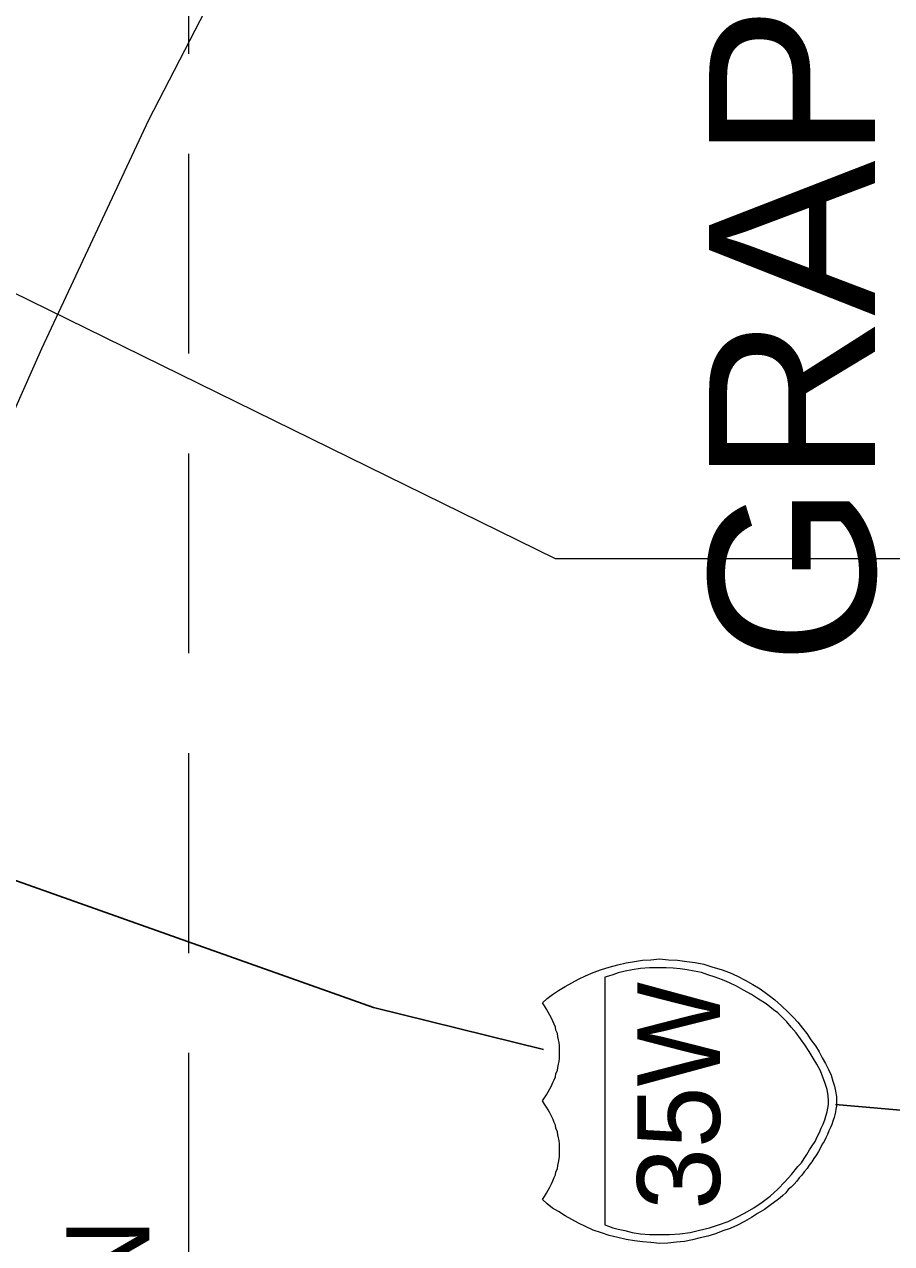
# Model space of a CAD drawing. Extents: x 2363323 to 2367082, y 6956018 to 6980837.
# Drawn here: x 2365838.7 to 2365892.1, y 6980582.6 to 6980657.7 of the extents above; entities that cross this region are included whole.
import ezdxf

# ---------------------------------------------------------------- set-up
doc = ezdxf.new("R2010")
doc.units = 0
doc.header["$LTSCALE"] = 4.1
doc.linetypes.add('MEDIUM_DASHED', pattern=[4.5, 3, -1.5])
doc.layers.add('62', color=7, linetype='Continuous', lineweight=13)
doc.layers.add('63', color=7, linetype='Continuous', lineweight=13)

msp = doc.modelspace()

# ---------------------------------------------------------------- linework, layer by layer
at = {"layer": '62', "linetype": 'MEDIUM_DASHED'}
msp.add_line((2365848.822, 6980834.218), (2365848.821, 6980385.954), dxfattribs=at)
at = {"layer": '62'}
msp.add_line((2365902.216, 6980624.792), (2365871.414, 6980624.792), dxfattribs=at)
at = {"layer": '62', "lineweight": 25}
for p, q in [((2365860.208, 6980597.16), (2365870.668, 6980594.571)), ((2365899.359, 6980590.251), (2365888.649, 6980591.198))]:
    msp.add_line(p, q, dxfattribs=at)
at = {"layer": '62'}
for points in [[(2365809.287, 6980449.612), (2365804.356, 6980460.212), (2365802.512, 6980474.5), (2365809.894, 6980490.59), (2365810.838, 6980501.526), (2365817.837, 6980515.14), (2365822.54, 6980524.522), (2365825.554, 6980532.603), (2365827.714, 6980543.964), (2365828.59, 6980553.189), (2365829.04, 6980565.342), (2365828.5, 6980579.562), (2365830.796, 6980597.678), (2365831.606, 6980609.468), (2365833.203, 6980622.902), (2365839.778, 6980637.732), (2365846.368, 6980651.814), (2365853.028, 6980664.688), (2365864.278, 6980679.314), (2365871.414, 6980689.148), (2365878.929, 6980701.188), (2365885.793, 6980708.072)], [(2365871.414, 6980624.792), (2365815.923, 6980652.02), (2365754.402, 6980665.14)], [(2365871.054, 6980592.164), (2365871.166, 6980592.345), (2365871.256, 6980592.548), (2365871.326, 6980592.704), (2365871.416, 6980592.906), (2365871.436, 6980593.108), (2365871.526, 6980593.288), (2365871.55, 6980593.468), (2365871.596, 6980593.67), (2365871.64, 6980593.85), (2365871.662, 6980594.054), (2365871.663, 6980594.234), (2365871.662, 6980594.436), (2365871.662, 6980594.616), (2365871.662, 6980594.796), (2365871.639, 6980595.02), (2365871.596, 6980595.178), (2365871.55, 6980595.358), (2365871.526, 6980595.562), (2365871.436, 6980595.764), (2365871.416, 6980595.945), (2365871.324, 6980596.148), (2365871.256, 6980596.328), (2365871.166, 6980596.508), (2365871.054, 6980596.689), (2365870.964, 6980596.869), (2365870.852, 6980597.07), (2365870.738, 6980597.272), (2365870.602, 6980597.451), (2365870.898, 6980597.722), (2365871.234, 6980597.972), (2365871.594, 6980598.218), (2365872, 6980598.465), (2365872.406, 6980598.69), (2365872.832, 6980598.916), (2365873.259, 6980599.118), (2365873.733, 6980599.322), (2365874.249, 6980599.502), (2365874.722, 6980599.658), (2365875.239, 6980599.792), (2365875.756, 6980599.906), (2365876.274, 6980599.995), (2365876.769, 6980600.085), (2365877.286, 6980600.108), (2365877.804, 6980600.154), (2365878.368, 6980600.108), (2365878.93, 6980600.085), (2365879.492, 6980599.995), (2365880.008, 6980599.928), (2365880.55, 6980599.838), (2365881.089, 6980599.658), (2365881.608, 6980599.502), (2365882.124, 6980599.322), (2365882.62, 6980599.095), (2365883.092, 6980598.849), (2365883.564, 6980598.578), (2365884.014, 6980598.308), (2365884.486, 6980597.97), (2365884.914, 6980597.632), (2365885.32, 6980597.272), (2365885.746, 6980596.869), (2365886.04, 6980596.575), (2365886.332, 6980596.26), (2365886.626, 6980595.9), (2365886.894, 6980595.56), (2365887.142, 6980595.178), (2365887.412, 6980594.796), (2365887.636, 6980594.436), (2365887.84, 6980594.076), (2365888.042, 6980593.716), (2365888.222, 6980593.356), (2365888.38, 6980592.998), (2365888.492, 6980592.636), (2365888.583, 6980592.32), (2365888.65, 6980592.006), (2365888.716, 6980591.692), (2365888.718, 6980591.421)], [(2365888.718, 6980591.421), (2365888.718, 6980591.241), (2365888.716, 6980591.084), (2365888.672, 6980590.905), (2365888.649, 6980590.746), (2365888.604, 6980590.566), (2365888.559, 6980590.386), (2365888.493, 6980590.161), (2365888.424, 6980589.96), (2365888.334, 6980589.778), (2365888.244, 6980589.576), (2365888.154, 6980589.351), (2365888.064, 6980589.148), (2365887.952, 6980588.925), (2365887.839, 6980588.744), (2365887.726, 6980588.518), (2365887.614, 6980588.295), (2365887.48, 6980588.091), (2365887.322, 6980587.868), (2365887.186, 6980587.664), (2365887.03, 6980587.462), (2365886.896, 6980587.258), (2365886.716, 6980587.054), (2365886.579, 6980586.852), (2365886.423, 6980586.672), (2365886.264, 6980586.47), (2365886.108, 6980586.29), (2365885.928, 6980586.11), (2365885.746, 6980585.954), (2365885.59, 6980585.75), (2365885.409, 6980585.592), (2365885.252, 6980585.457), (2365885.05, 6980585.3), (2365884.689, 6980585.03), (2365884.286, 6980584.737), (2365883.856, 6980584.491), (2365883.474, 6980584.24), (2365883.046, 6980583.994), (2365882.62, 6980583.771), (2365882.17, 6980583.567), (2365881.719, 6980583.41), (2365881.27, 6980583.23), (2365880.796, 6980583.093), (2365880.326, 6980582.982), (2365879.852, 6980582.87), (2365879.358, 6980582.758), (2365878.863, 6980582.712), (2365878.322, 6980582.667), (2365877.804, 6980582.644), (2365877.286, 6980582.69), (2365876.77, 6980582.736), (2365876.274, 6980582.804), (2365875.756, 6980582.892), (2365875.239, 6980583.004), (2365874.723, 6980583.14), (2365874.249, 6980583.297), (2365873.732, 6980583.454), (2365873.26, 6980583.68), (2365872.833, 6980583.88), (2365872.406, 6980584.107), (2365871.999, 6980584.332), (2365871.596, 6980584.602), (2365871.234, 6980584.806), (2365870.896, 6980585.074), (2365870.604, 6980585.344), (2365870.738, 6980585.526), (2365870.852, 6980585.728), (2365870.964, 6980585.93), (2365871.056, 6980586.11), (2365871.166, 6980586.312), (2365871.256, 6980586.492), (2365871.326, 6980586.694), (2365871.416, 6980586.874), (2365871.438, 6980587.053), (2365871.526, 6980587.236), (2365871.549, 6980587.438), (2365871.594, 6980587.618), (2365871.639, 6980587.842), (2365871.663, 6980588.001), (2365871.662, 6980588.182), (2365871.663, 6980588.406), (2365871.663, 6980588.584), (2365871.663, 6980588.766), (2365871.64, 6980588.97), (2365871.596, 6980589.148), (2365871.549, 6980589.328), (2365871.526, 6980589.508), (2365871.438, 6980589.735), (2365871.414, 6980589.914), (2365871.324, 6980590.094), (2365871.258, 6980590.274), (2365871.168, 6980590.476), (2365871.054, 6980590.678), (2365870.964, 6980590.858), (2365870.852, 6980591.04), (2365870.738, 6980591.218), (2365870.601, 6980591.421), (2365870.738, 6980591.602), (2365870.853, 6980591.78), (2365870.966, 6980591.984), (2365871.054, 6980592.164)]]:
    msp.add_lwpolyline(points, dxfattribs=at)
at = {"layer": '62', "lineweight": 25}
msp.add_lwpolyline([(2365753.974, 6980646.213), (2365755.146, 6980645.47), (2365784.062, 6980634.536), (2365810.86, 6980619.3), (2365829.356, 6980608.095), (2365860.208, 6980597.16)], dxfattribs=at)
at = {"layer": '62'}
msp.add_lwpolyline([(2365874.453, 6980599.028), (2365874.452, 6980583.794), (2365874.678, 6980583.704), (2365874.946, 6980583.612), (2365875.263, 6980583.524), (2365875.689, 6980583.432), (2365876.14, 6980583.321), (2365876.634, 6980583.23), (2365877.196, 6980583.184), (2365877.806, 6980583.184), (2365878.436, 6980583.184), (2365879.064, 6980583.23), (2365879.694, 6980583.32), (2365880.279, 6980583.454), (2365880.885, 6980583.612), (2365881.448, 6980583.792), (2365882.034, 6980583.993), (2365882.574, 6980584.264), (2365883.093, 6980584.534), (2365883.632, 6980584.827), (2365884.126, 6980585.187), (2365884.623, 6980585.547), (2365885.094, 6980585.974), (2365885.523, 6980586.424), (2365885.949, 6980586.876), (2365886.332, 6980587.371), (2365886.556, 6980587.596), (2365886.714, 6980587.866), (2365886.894, 6980588.114), (2365887.053, 6980588.406), (2365887.21, 6980588.655), (2365887.389, 6980588.924), (2365887.524, 6980589.195), (2365887.659, 6980589.464), (2365887.773, 6980589.734), (2365887.884, 6980589.982), (2365887.996, 6980590.251), (2365888.064, 6980590.476), (2365888.132, 6980590.746), (2365888.178, 6980590.971), (2365888.222, 6980591.194), (2365888.222, 6980591.421), (2365888.199, 6980591.734), (2365888.132, 6980592.118), (2365888.018, 6980592.478), (2365887.862, 6980592.884), (2365887.726, 6980593.266), (2365887.502, 6980593.671), (2365887.276, 6980594.055), (2365887.029, 6980594.46), (2365886.759, 6980594.865), (2365886.49, 6980595.246), (2365886.22, 6980595.608), (2365885.926, 6980595.945), (2365885.656, 6980596.281), (2365885.364, 6980596.575), (2365885.096, 6980596.846), (2365884.826, 6980597.025), (2365884.374, 6980597.386), (2365883.902, 6980597.678), (2365883.472, 6980597.97), (2365882.979, 6980598.24), (2365882.552, 6980598.488), (2365882.124, 6980598.69), (2365881.696, 6980598.87), (2365881.246, 6980599.028), (2365880.798, 6980599.185), (2365880.392, 6980599.32), (2365879.942, 6980599.41), (2365879.514, 6980599.479), (2365879.086, 6980599.545), (2365878.659, 6980599.592), (2365878.232, 6980599.612), (2365877.806, 6980599.612), (2365877.198, 6980599.612), (2365876.634, 6980599.569), (2365876.14, 6980599.478), (2365875.69, 6980599.41), (2365875.263, 6980599.298), (2365874.946, 6980599.186), (2365874.676, 6980599.096)], close=True, dxfattribs=at)
at = {"layer": '63', "linetype": 'MEDIUM_DASHED'}
msp.add_line((2365848.822, 6980834.218), (2365848.821, 6980385.954), dxfattribs=at)
at = {"layer": '63'}
msp.add_line((2365902.216, 6980624.792), (2365871.414, 6980624.792), dxfattribs=at)
at = {"layer": '63', "lineweight": 25}
for p, q in [((2365860.208, 6980597.16), (2365870.668, 6980594.571)), ((2365899.359, 6980590.251), (2365888.649, 6980591.198))]:
    msp.add_line(p, q, dxfattribs=at)
at = {"layer": '63'}
for points in [[(2365809.287, 6980449.612), (2365804.356, 6980460.212), (2365802.512, 6980474.5), (2365809.894, 6980490.59), (2365810.838, 6980501.526), (2365817.837, 6980515.14), (2365822.54, 6980524.522), (2365825.554, 6980532.603), (2365827.714, 6980543.964), (2365828.59, 6980553.189), (2365829.04, 6980565.342), (2365828.5, 6980579.562), (2365830.796, 6980597.678), (2365831.606, 6980609.468), (2365833.203, 6980622.902), (2365839.778, 6980637.732), (2365846.368, 6980651.814), (2365853.028, 6980664.688), (2365864.278, 6980679.314), (2365871.414, 6980689.148), (2365878.929, 6980701.188), (2365885.793, 6980708.072)], [(2365871.414, 6980624.792), (2365815.923, 6980652.02), (2365754.402, 6980665.14)], [(2365871.054, 6980592.164), (2365871.166, 6980592.345), (2365871.256, 6980592.548), (2365871.326, 6980592.704), (2365871.416, 6980592.906), (2365871.436, 6980593.108), (2365871.526, 6980593.288), (2365871.55, 6980593.468), (2365871.596, 6980593.67), (2365871.64, 6980593.85), (2365871.662, 6980594.054), (2365871.663, 6980594.234), (2365871.662, 6980594.436), (2365871.662, 6980594.616), (2365871.662, 6980594.796), (2365871.639, 6980595.02), (2365871.596, 6980595.178), (2365871.55, 6980595.358), (2365871.526, 6980595.562), (2365871.436, 6980595.764), (2365871.416, 6980595.945), (2365871.324, 6980596.148), (2365871.256, 6980596.328), (2365871.166, 6980596.508), (2365871.054, 6980596.689), (2365870.964, 6980596.869), (2365870.852, 6980597.07), (2365870.738, 6980597.272), (2365870.602, 6980597.451), (2365870.898, 6980597.722), (2365871.234, 6980597.972), (2365871.594, 6980598.218), (2365872, 6980598.465), (2365872.406, 6980598.69), (2365872.832, 6980598.916), (2365873.259, 6980599.118), (2365873.733, 6980599.322), (2365874.249, 6980599.502), (2365874.722, 6980599.658), (2365875.239, 6980599.792), (2365875.756, 6980599.906), (2365876.274, 6980599.995), (2365876.769, 6980600.085), (2365877.286, 6980600.108), (2365877.804, 6980600.154), (2365878.368, 6980600.108), (2365878.93, 6980600.085), (2365879.492, 6980599.995), (2365880.008, 6980599.928), (2365880.55, 6980599.838), (2365881.089, 6980599.658), (2365881.608, 6980599.502), (2365882.124, 6980599.322), (2365882.62, 6980599.095), (2365883.092, 6980598.849), (2365883.564, 6980598.578), (2365884.014, 6980598.308), (2365884.486, 6980597.97), (2365884.914, 6980597.632), (2365885.32, 6980597.272), (2365885.746, 6980596.869), (2365886.04, 6980596.575), (2365886.332, 6980596.26), (2365886.626, 6980595.9), (2365886.894, 6980595.56), (2365887.142, 6980595.178), (2365887.412, 6980594.796), (2365887.636, 6980594.436), (2365887.84, 6980594.076), (2365888.042, 6980593.716), (2365888.222, 6980593.356), (2365888.38, 6980592.998), (2365888.492, 6980592.636), (2365888.583, 6980592.32), (2365888.65, 6980592.006), (2365888.716, 6980591.692), (2365888.718, 6980591.421)], [(2365888.718, 6980591.421), (2365888.718, 6980591.241), (2365888.716, 6980591.084), (2365888.672, 6980590.905), (2365888.649, 6980590.746), (2365888.604, 6980590.566), (2365888.559, 6980590.386), (2365888.493, 6980590.161), (2365888.424, 6980589.96), (2365888.334, 6980589.778), (2365888.244, 6980589.576), (2365888.154, 6980589.351), (2365888.064, 6980589.148), (2365887.952, 6980588.925), (2365887.839, 6980588.744), (2365887.726, 6980588.518), (2365887.614, 6980588.295), (2365887.48, 6980588.091), (2365887.322, 6980587.868), (2365887.186, 6980587.664), (2365887.03, 6980587.462), (2365886.896, 6980587.258), (2365886.716, 6980587.054), (2365886.579, 6980586.852), (2365886.423, 6980586.672), (2365886.264, 6980586.47), (2365886.108, 6980586.29), (2365885.928, 6980586.11), (2365885.746, 6980585.954), (2365885.59, 6980585.75), (2365885.409, 6980585.592), (2365885.252, 6980585.457), (2365885.05, 6980585.3), (2365884.689, 6980585.03), (2365884.286, 6980584.737), (2365883.856, 6980584.491), (2365883.474, 6980584.24), (2365883.046, 6980583.994), (2365882.62, 6980583.771), (2365882.17, 6980583.567), (2365881.719, 6980583.41), (2365881.27, 6980583.23), (2365880.796, 6980583.093), (2365880.326, 6980582.982), (2365879.852, 6980582.87), (2365879.358, 6980582.758), (2365878.863, 6980582.712), (2365878.322, 6980582.667), (2365877.804, 6980582.644), (2365877.286, 6980582.69), (2365876.77, 6980582.736), (2365876.274, 6980582.804), (2365875.756, 6980582.892), (2365875.239, 6980583.004), (2365874.723, 6980583.14), (2365874.249, 6980583.297), (2365873.732, 6980583.454), (2365873.26, 6980583.68), (2365872.833, 6980583.88), (2365872.406, 6980584.107), (2365871.999, 6980584.332), (2365871.596, 6980584.602), (2365871.234, 6980584.806), (2365870.896, 6980585.074), (2365870.604, 6980585.344), (2365870.738, 6980585.526), (2365870.852, 6980585.728), (2365870.964, 6980585.93), (2365871.056, 6980586.11), (2365871.166, 6980586.312), (2365871.256, 6980586.492), (2365871.326, 6980586.694), (2365871.416, 6980586.874), (2365871.438, 6980587.053), (2365871.526, 6980587.236), (2365871.549, 6980587.438), (2365871.594, 6980587.618), (2365871.639, 6980587.842), (2365871.663, 6980588.001), (2365871.662, 6980588.182), (2365871.663, 6980588.406), (2365871.663, 6980588.584), (2365871.663, 6980588.766), (2365871.64, 6980588.97), (2365871.596, 6980589.148), (2365871.549, 6980589.328), (2365871.526, 6980589.508), (2365871.438, 6980589.735), (2365871.414, 6980589.914), (2365871.324, 6980590.094), (2365871.258, 6980590.274), (2365871.168, 6980590.476), (2365871.054, 6980590.678), (2365870.964, 6980590.858), (2365870.852, 6980591.04), (2365870.738, 6980591.218), (2365870.601, 6980591.421), (2365870.738, 6980591.602), (2365870.853, 6980591.78), (2365870.966, 6980591.984), (2365871.054, 6980592.164)]]:
    msp.add_lwpolyline(points, dxfattribs=at)
at = {"layer": '63', "lineweight": 25}
msp.add_lwpolyline([(2365753.974, 6980646.213), (2365755.146, 6980645.47), (2365784.062, 6980634.536), (2365810.86, 6980619.3), (2365829.356, 6980608.095), (2365860.208, 6980597.16)], dxfattribs=at)
at = {"layer": '63'}
msp.add_lwpolyline([(2365874.453, 6980599.028), (2365874.452, 6980583.794), (2365874.678, 6980583.704), (2365874.946, 6980583.612), (2365875.263, 6980583.524), (2365875.689, 6980583.432), (2365876.14, 6980583.321), (2365876.634, 6980583.23), (2365877.196, 6980583.184), (2365877.806, 6980583.184), (2365878.436, 6980583.184), (2365879.064, 6980583.23), (2365879.694, 6980583.32), (2365880.279, 6980583.454), (2365880.885, 6980583.612), (2365881.448, 6980583.792), (2365882.034, 6980583.993), (2365882.574, 6980584.264), (2365883.093, 6980584.534), (2365883.632, 6980584.827), (2365884.126, 6980585.187), (2365884.623, 6980585.547), (2365885.094, 6980585.974), (2365885.523, 6980586.424), (2365885.949, 6980586.876), (2365886.332, 6980587.371), (2365886.556, 6980587.596), (2365886.714, 6980587.866), (2365886.894, 6980588.114), (2365887.053, 6980588.406), (2365887.21, 6980588.655), (2365887.389, 6980588.924), (2365887.524, 6980589.195), (2365887.659, 6980589.464), (2365887.773, 6980589.734), (2365887.884, 6980589.982), (2365887.996, 6980590.251), (2365888.064, 6980590.476), (2365888.132, 6980590.746), (2365888.178, 6980590.971), (2365888.222, 6980591.194), (2365888.222, 6980591.421), (2365888.199, 6980591.734), (2365888.132, 6980592.118), (2365888.018, 6980592.478), (2365887.862, 6980592.884), (2365887.726, 6980593.266), (2365887.502, 6980593.671), (2365887.276, 6980594.055), (2365887.029, 6980594.46), (2365886.759, 6980594.865), (2365886.49, 6980595.246), (2365886.22, 6980595.608), (2365885.926, 6980595.945), (2365885.656, 6980596.281), (2365885.364, 6980596.575), (2365885.096, 6980596.846), (2365884.826, 6980597.025), (2365884.374, 6980597.386), (2365883.902, 6980597.678), (2365883.472, 6980597.97), (2365882.979, 6980598.24), (2365882.552, 6980598.488), (2365882.124, 6980598.69), (2365881.696, 6980598.87), (2365881.246, 6980599.028), (2365880.798, 6980599.185), (2365880.392, 6980599.32), (2365879.942, 6980599.41), (2365879.514, 6980599.479), (2365879.086, 6980599.545), (2365878.659, 6980599.592), (2365878.232, 6980599.612), (2365877.806, 6980599.612), (2365877.198, 6980599.612), (2365876.634, 6980599.569), (2365876.14, 6980599.478), (2365875.69, 6980599.41), (2365875.263, 6980599.298), (2365874.946, 6980599.186), (2365874.676, 6980599.096)], close=True, dxfattribs=at)

# ---------------------------------------------------------------- texts
at = {"layer": '62', "width": 1.05}
msp.add_text('GRAPEVINE', height=10.21, rotation=90, dxfattribs=at).set_placement((2365891.079, 6980618.242))
at = {"layer": '62'}
for s, p in [('35W', (2365881.538, 6980584.716)), ('DENTON', (2365846.391, 6980555.374))]:
    msp.add_text(s, height=5.099, rotation=90, dxfattribs=at).set_placement(p)
at = {"layer": '63', "width": 1.05}
msp.add_text('GRAPEVINE', height=10.21, rotation=90, dxfattribs=at).set_placement((2365891.079, 6980618.242))
at = {"layer": '63'}
for s, p in [('35W', (2365881.538, 6980584.716)), ('DENTON', (2365846.391, 6980555.374))]:
    msp.add_text(s, height=5.099, rotation=90, dxfattribs=at).set_placement(p)

doc.saveas('drawing.dxf')
